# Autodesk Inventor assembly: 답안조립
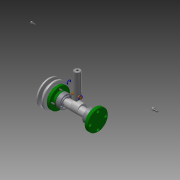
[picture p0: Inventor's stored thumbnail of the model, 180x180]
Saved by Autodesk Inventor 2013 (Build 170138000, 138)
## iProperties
Created: 2016-01
Part Number: 답안조립
Document SubType Name: Assembly
Designer: Administrator
Author: Administrator
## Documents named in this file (19)
- C:\Users\Administrator\Desktop\460127V1008\답안조립.iam
- C:\Users\Administrator\Desktop\460127V1008\본체.ipt
- C:\Users\Administrator\Desktop\460127V1008\V-벨트풀리.ipt
- C:\Users\Administrator\Desktop\460127V1008\고정핀.ipt
- C:\Users\Administrator\Desktop\460127V1008\뒤커버.ipt
- C:\Users\Administrator\Desktop\460127V1008\링크.ipt
- C:\Users\Administrator\Desktop\460127V1008\멈춤링 6 x 5.ipt
- C:\Users\Administrator\Desktop\460127V1008\멈춤링 15 x 1.ipt
- C:\Users\Administrator\Desktop\460127V1008\베어링 15 x 35 x 11.ipt
- C:\Users\Administrator\Desktop\460127V1008\볼트 M3 x 8.ipt
- C:\Users\Administrator\Desktop\460127V1008\볼트 M4 x 10.ipt
- C:\Users\Administrator\Desktop\460127V1008\볼트 M6 x 12.ipt
- C:\Users\Administrator\Desktop\460127V1008\상부부시.ipt
- C:\Users\Administrator\Desktop\460127V1008\슬라이드바.ipt
- C:\Users\Administrator\Desktop\460127V1008\앞커버.ipt
- C:\Users\Administrator\Desktop\460127V1008\오일실 15 25 7.ipt
- C:\Users\Administrator\Desktop\460127V1008\와셔.ipt
- C:\Users\Administrator\Desktop\460127V1008\키 5 x 5 x 14.ipt
- C:\Users\Administrator\Desktop\460127V1008\편심축.ipt
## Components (9 placed, 5 different names)
1. V-벨트풀리:1 — 각도:2
2. 고정핀:1
3. ISO 4762 M3 x 8:1
4. ISO 4018 M6 x 12:1
5. ISO 4762 M4 x 10:2
6. ISO 4762 M4 x 10:1
7. ISO 4762 M4 x 10:3
8. ISO 4762 M4 x 10:4
9. ISO 4762 M4 x 10:5
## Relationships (1: Angle 1)
- 각도:2 [Angle]: V-벨트풀리:1
